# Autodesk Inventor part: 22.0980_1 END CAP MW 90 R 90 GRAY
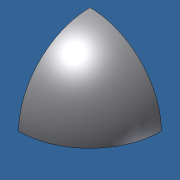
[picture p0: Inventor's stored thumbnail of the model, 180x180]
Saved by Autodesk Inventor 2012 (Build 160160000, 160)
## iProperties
Created: 2014-06
Part Number: 22.0980_1 END CAP MW 90 R 90 GRAY
Material: Default
Document SubType Name: Modeling
Designer: Admin
Density: 1 g/cm^3
Mass: 28.0022 g
Surface Area: 275.087 cm^2
Volume: 28.0022 cm^3
Translation Standard: STEP AP214IS
FileName: 21_2199_0_1.stp
PreProcessor: ACIS
PostProcessor: Build: 160, Release: 2012 RTM - Date: Tue 03/01/2011
Sent Units: millimeter
Uncertainty: 0.0
Author: Admin
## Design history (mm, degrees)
feature "Base1"
workplane "Work Plane3"
sketch "Sketch2"
  geometry: C1 r 4 at (62.225, 35.926); 1 further point
  constraints: 1 centre point, 1 coincident
  dimensions: "d4" = 8 diameter of C1
extrude "Extrusion2" join sketch "Sketch2" distance "d5" = 10; taper "d6" = 0 deg
sketch "Sketch3"
  geometry: C1 r 4 at (0, 0) reference; C2 r 2.5 at (0, 0)
  constraints: 1 centre point, 1 coincident
  dimensions: "d7" = 5 diameter of C2
extrude "Extrusion3" join sketch "Sketch3" distance "d8" = 38; taper "d9" = 0 deg
sketch "Sketch4"
  geometry: C1 r 4 at (0, 0) reference
extrude "Extrusion4" join sketch "Sketch4" stored distance "d10" = 15; taper "d11" = 0 deg
body "Solid1"
